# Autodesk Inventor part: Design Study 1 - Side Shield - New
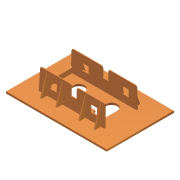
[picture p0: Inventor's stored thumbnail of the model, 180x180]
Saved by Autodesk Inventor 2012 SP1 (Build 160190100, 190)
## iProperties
Created: 2012-03
Part Number: Design Study 1 - Side Shield - New
Material: Default
Document SubType Name: Modeling
Designer: dmm70056
Density: 1 g/cm^3
Mass: 17.0823 g
Surface Area: 209.162 cm^2
Volume: 17.0823 cm^3
Author: dmm70056
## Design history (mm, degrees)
sketch "Sketch1"
  geometry: L1 (-52.5, 35)-(52.5, 35); L2 (52.5, 35)-(52.5, -35); L3 (52.5, -35)-(-52.5, -35); L4 (-52.5, -35)-(-52.5, 35); 1 further point
  constraints: 8 end point, 2 parallel, 1 horizontal, 1 perpendicular
  dimensions: "d0" = 70 distance of L3.end L1.start; "d1" = 105 distance of L2.end L3.end; "d2" = 52.5 distance from line of point (0, 0) L4 (= 0.5 x d1); "d3" = 35 distance from line of L3 point (0, 0) (= 0.5 x d0)
extrude "Extrusion1" new body sketch "Sketch1" distance "d4" = 2; taper "d5" = 0 deg
sketch "Sketch2"
  geometry: L1 (-23, 5.5)-(-23, -5.5); L2 (-11, -5.5)-(-11, 5.5); L3 (11, 5.5)-(11, -5.5); L4 (23, -5.5)-(23, 5.5); L5 (-17, 5.5)-(17, 5.5); L6 (17, 5.5)-(17, -5.5); L7 (17, -5.5)-(-17, -5.5); L8 (-17, -5.5)-(-17, 5.5); A1 r 6 centre (-17, -5.5) between (-23, -5.5) and (-11, -5.5); A2 r 6 centre (-17, 5.5) between (-11, 5.5) and (-23, 5.5); A3 r 6 centre (17, -5.5) between (11, -5.5) and (23, -5.5); A4 r 6 centre (17, 5.5) between (23, 5.5) and (11, 5.5); 1 further point
  constraints: 16 end point, 8 point on circle, 8 tangent, 5 parallel, 4 centre point, 2 horizontal alignment, 1 equal radius, 1 horizontal, 1 perpendicular, 1 vertical
  dimensions: "d6" = 34 distance of A4.centre L5.start; "d7" = 17 horizontal distance of L5.start point (0, 0) (= 0.5 x d6); "d8" = 6 radius of A2; "d9" = 11 distance of A1.centre L5.start; "d10" = 5.5 vertical distance of point (0, 0) L5.start (= 0.5 x d9)
extrude "Extrusion2" cut sketch "Sketch2" stored distance "d11" = 2; taper "d12" = 0 deg
sketch "Sketch3"
  geometry: L1 (-34.5, 16)-(-34.5, -16); L2 (-34.5, -16)-(32.5, -16); L3 (32.5, -16)-(32.5, -17.5); L4 (32.5, -17.5)-(-36, -17.5); L5 (-36, -17.5)-(-36, 17.5); L6 (-36, 17.5)-(32.5, 17.5); L7 (32.5, 17.5)-(32.5, 16); L8 (32.5, 16)-(-34.5, 16); 1 further point
  constraints: 16 end point, 6 parallel, 2 collinear, 1 perpendicular, 1 vertical
  dimensions: "d14" = 67 distance between parallel lines of L1 L3; "d16" = 1.5 distance between parallel lines of L5 L1; "d17" = 1.5 distance between parallel lines of L2 L4; "d18" = 32 distance of L1.start L1.end; "d19" = 16 distance from line of point (0, 0) L8 (= 0.5 x d18); "d59" = 34.5 distance from line of L1 point (0, 0)
extrude "Extrusion3" join sketch "Sketch3" distance "d20" = 22; taper "d21" = 0 deg
sketch "Sketch4"
  geometry: L1 (1.5, 22)-(68.5, 22) reference; L2 (68.5, 22)-(1.5, 22) reference; L3 (0, 22)-(68.5, 22) reference; L4 (68.5, 22)-(0, 22) reference; L5 (1.5, 0)-(1.5, 22) reference; L6 (1.5, 0)-(1.5, 22) reference; L7 (33, 22)-(39, 22); L8 (39, 22)-(39, 11.5); L9 (39, 11.5)-(33, 11.5); L10 (33, 11.5)-(33, 22); L11 (1.5, 0)-(68.5, 0) reference; L12 (68.5, 0)-(0, 0) reference; L13 (0, 0)-(68.5, 0) reference; L14 (68.5, 0)-(1.5, 0) reference; L15 (47, 0)-(25, 0) reference; L16 (25, 0)-(13, 0) reference; L17 (13, 0)-(25, 0) reference; L18 (25, 0)-(47, 0) reference; L19 (47, 0)-(59, 0) reference; L20 (59, 0)-(47, 0) reference; L21 (-16.5, 0)-(88.5, 0) reference; L22 (88.5, 0)-(-16.5, 0) reference; 1 further point
  constraints: 8 end point, 2 parallel, 1 horizontal, 1 perpendicular, 1 point on line
  dimensions: "d22" = 6 distance between parallel lines of L10 L8; "d23" = 11.5 distance between parallel lines of L12 L9; "d24" = 31.5 distance between parallel lines of L10 L5
extrude "Extrusion4" cut sketch "Sketch4" stored distance "d25" = 21.5; taper "d26" = 0 deg
sketch "Sketch5"
  geometry: L1 (11.5, 14.5)-(18.5, 14.5); L2 (18.5, 14.5)-(18.5, 7.5); L3 (18.5, 7.5)-(11.5, 7.5); L4 (11.5, 7.5)-(11.5, 14.5); L5 (53.5, 14.5)-(60.5, 14.5); L6 (60.5, 14.5)-(60.5, 7.5); L7 (60.5, 7.5)-(53.5, 7.5); L8 (53.5, 7.5)-(53.5, 14.5); L9 (39, 11.5)-(33, 11.5) reference; L10 (1.5, 0)-(1.5, 22) reference; L11 (1.5, 0)-(1.5, 22) reference; 1 further point
  constraints: 16 end point, 4 parallel, 2 collinear, 2 horizontal, 2 perpendicular
  dimensions: "d27" = 7 distance of L2.end L3.end; "d28" = 7 distance of L3.end L1.start; "d29" = 7 distance of L6.end L7.end; "d30" = 3 distance between parallel lines of L9 L1; "d31" = 35 distance between parallel lines of L8 L2; "d32" = 10 distance between parallel lines of L4 L10
extrude "Extrusion5" cut sketch "Sketch5" stored distance "d33" = 21.5; taper "d34" = 0 deg
workplane "Work Plane1"
workplane "Work Plane3"
workplane "Work Plane4"
workplane "Work Plane5"
sketch "Sketch9"
  geometry: L1 (-11.5, 1.5)-(-11.5, 0) reference; L2 (-11.5, 0)-(-11.5, 35) reference; L3 (-11.5, 35)-(-11.5, 33.5) reference; L4 (-11.5, 33.5)-(-11.5, 1.5) reference; L5 (-11.5, 23)-(-11.5, 23) reference; L6 (-11.5, 23)-(-11.5, 12) reference; L7 (-11.5, 12)-(-11.5, 12) reference; L8 (-11.5, 12)-(-11.5, 12) reference; L9 (-11.5, 12)-(-11.5, 23) reference; L10 (-11.5, 23)-(-11.5, 23) reference; L11 (-11.5, -17.5)-(-11.5, 52.5) reference; L12 (-11.5, 52.5)-(-11.5, -17.5) reference; L13 (-4, 0)-(3, 0) reference; L14 (3, 0)-(-4, 0) reference; L15 (-4, 0)-(3, 0) reference; L16 (3, 0)-(-4, 0) reference; L17 (10.5, 0)-(0, 0) reference; L18 (0, 0)-(10.5, 0) reference; L19 (-11.5, 0)-(10.5, 0) reference; L20 (-11.5, 0)-(10.5, 0) reference; L21 (10.5, 0)-(10.5, 1.5) reference; L22 (10.5, 33.5)-(10.5, 1.5) reference; L23 (10.5, 33.5)-(10.5, 35) reference; L24 (10.5, 0)-(10.5, 35) reference; L25 (6.5, 0)-(-11.5, -6); 1 further point
  constraints: 2 end point, 2 point on line
  dimensions: "d67" = 4 distance from line of L24 L25.start; "d68" = 6 distance from line of L19 L25.end
feature "Rib3" sketch "Sketch9" dims "d69" = 1, "d70" = 1.5, "d71" = 0, "d72" = 0, "d73" = 1, "d74" = 1
sketch "Sketch10"
  geometry: L1 (-11.5, -17.5)-(-11.5, 52.5) reference; L2 (-11.5, 52.5)-(-11.5, -17.5) reference; L3 (-11.5, 23)-(-11.5, 23) reference; L4 (-11.5, 23)-(-11.5, 12) reference; L5 (-11.5, 12)-(-11.5, 12) reference; L6 (-11.5, 12)-(-11.5, 12) reference; L7 (-11.5, 12)-(-11.5, 23) reference; L8 (-11.5, 23)-(-11.5, 23) reference; L9 (-11.5, 33.5)-(-11.5, 1.5) reference; L10 (-11.5, 1.5)-(-11.5, 0) reference; L11 (-11.5, 0)-(-11.5, -6) reference; L12 (-11.5, -6)-(-11.5, 0) reference; L13 (-11.5, 0)-(-11.5, 35) reference; L14 (-11.5, 35)-(-11.5, 33.5) reference; L15 (6.5, 0)-(-11.5, 0) reference; L16 (-11.5, 0)-(10.5, 0) reference; L17 (10.5, 0)-(0, 0) reference; L18 (0, 0)-(10.5, 0) reference; L19 (-11.5, 0)-(10.5, 0) reference; L20 (-11.5, 0)-(6.5, 0) reference; L21 (-4, 0)-(3, 0) reference; L22 (3, 0)-(-4, 0) reference; L23 (-4, 0)-(3, 0) reference; L24 (3, 0)-(-4, 0) reference; L25 (10.5, 0)-(10.5, 35) reference; L26 (10.5, 0)-(10.5, 1.5) reference; L27 (10.5, 33.5)-(10.5, 1.5) reference; L28 (10.5, 33.5)-(10.5, 35) reference; L29 (6.5, 0)-(-11.5, -6); 1 further point
  constraints: 2 end point, 2 point on line
  dimensions: "d75" = 4 distance from line of L25 L29.start; "d76" = 6 distance from line of L20 L29.end
feature "Rib4" sketch "Sketch10" dims "d77" = 1, "d78" = 1.5, "d79" = 0, "d80" = 0, "d81" = 1, "d82" = 1
sketch "Sketch8"
  geometry: L1 (0, 32)-(0, 0) reference; L2 (0, 32)-(-22, 32) reference; L3 (-22, 32)-(-22, 0) reference; L4 (0, 0)-(-22, 0) reference; L5 (-22, 32)-(-5, 32); L6 (-5, 32)-(-5, 0); L7 (-5, 0)-(-22, 0); L8 (-22, 0)-(-22, 32); 1 further point
  constraints: 8 end point, 2 parallel, 1 horizontal, 1 perpendicular, 1 point on line
  dimensions: "d63" = 5 distance between parallel lines of L1 L6
extrude "Extrusion6" cut sketch "Sketch8" stored distance "d61" = 10; taper "d62" = 0 deg
fillet "Fillet1" dims "d64" = 2
feature "FaceDraft4" dims angle "d84" = 1 deg
feature "FaceDraft5" dims angle "d85" = 1 deg
mirror "Mirror4"
mirror "Mirror5"
feature "FaceDraft6" dims angle "d86" = 2 deg
fillet "Fillet2" dims "d87" = 2
fillet "Fillet3" dims "d88" = 2
body "Solid1"
node "Projected Loop1"
node "Projected Loop2"
node "Projected Loop3"
node "Projected Loop4"
node "Projected Loop11"
node "Projected Loop12"
node "Projected Loop13"
node "Projected Loop14"
node "Projected Loop15"
node "Projected Loop16"
node "Projected Loop17"
other parameters: "d65" = 28, "d66" = 12
